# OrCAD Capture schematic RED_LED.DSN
size A
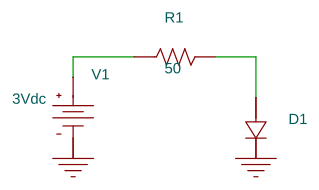
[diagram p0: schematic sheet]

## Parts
D1  Dbreak
R1  50  [AX/RC05]
V1  VDC

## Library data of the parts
D1 = Dbreak
R1 = R
V1 = VDC: DC: 3Vdc

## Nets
0: D1.1(2) V1.1(-)
N00092: D1.0(1) R1.2
N00099: R1.1 V1.0(+)
